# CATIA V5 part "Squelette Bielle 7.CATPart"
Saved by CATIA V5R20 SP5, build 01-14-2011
Part number: Squelette Bielle 7
Bounding box of the stored display mesh (mm): x -290 to -220, y -300 to -200, z -30 to 110
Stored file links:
  U:\CFAO\Thinkmotion\Squelette Bielle 7.CATPart
  U:\CFAO\Thinkmotion\Bras Articule.CATProduct
  U:\CFAO\Thinkmotion\Squelette general.CATPart
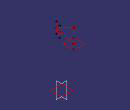
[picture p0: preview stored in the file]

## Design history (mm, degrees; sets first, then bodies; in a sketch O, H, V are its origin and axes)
Set1
  Line1: type PtPt, FirstPoint Point1, SecondPoint Point2
  Line2: type Normal, RefPoint Point1, RefSkin Plane2, Start -30, End 30
  Line3: type Normal, RefPoint Point2, RefSkin Plane2, Start -30, End 30
  Plane1: type OffsetPt, RefPlane xy-plane, RefPoint Point1
  Line4: type PtPt, FirstPoint Point1, SecondPoint Point3
  Line5: type PtPt, FirstPoint Point3, SecondPoint Point4
  Line6: type Normal, RefPoint Point4, RefSkin xy-plane, Start -30, End 30
Set2
  Point1: linked copy from another document
  Point2: linked copy from another document
  Plane2: linked copy from another document
  Point3: linked copy from another document
  Point4: linked copy from another document
Body1 (main body)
